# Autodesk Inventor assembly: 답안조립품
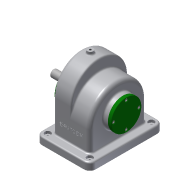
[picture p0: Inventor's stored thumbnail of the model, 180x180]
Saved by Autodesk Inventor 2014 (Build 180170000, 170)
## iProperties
Created: 2017-11
Part Number: 답안조립품
Document SubType Name: Assembly
Designer: user
Author: user
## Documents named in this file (14)
- C:\Users\user\Desktop\471108V1004\답안조립품.iam
- C:\Users\user\Desktop\471108V1004\본체.ipt
- C:\Users\user\Desktop\471108V1004\앞커버.ipt
- C:\Users\user\Desktop\471108V1004\오일 실 15 30 7.ipt
- C:\Users\user\Desktop\471108V1004\베어링 6002.ipt
- C:\Users\user\Desktop\471108V1004\축.ipt
- C:\Users\user\Desktop\471108V1004\키 - 6 x 6 x 22.ipt
- C:\Users\user\Desktop\471108V1004\스퍼기어.ipt
- C:\Users\user\Desktop\471108V1004\뒤커버.ipt
- C:\Users\user\Desktop\471108V1004\볼트 M3 x 8.ipt
- C:\Users\user\Desktop\471108V1004\V-벨트풀리.ipt
- C:\Users\user\Desktop\471108V1004\멈춤나사 - M4 x 10.ipt
- 멈춤나사 - M4 x 10.ipt
- C:\Users\user\Desktop\471108V1004\키 - 5 x 5 x 18.ipt
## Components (1 placed, 1 different names)
1. V-벨트풀리:1 — 플러쉬:1
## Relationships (1: Flush 1)
- 플러쉬:1 [Flush]: V-벨트풀리:1
